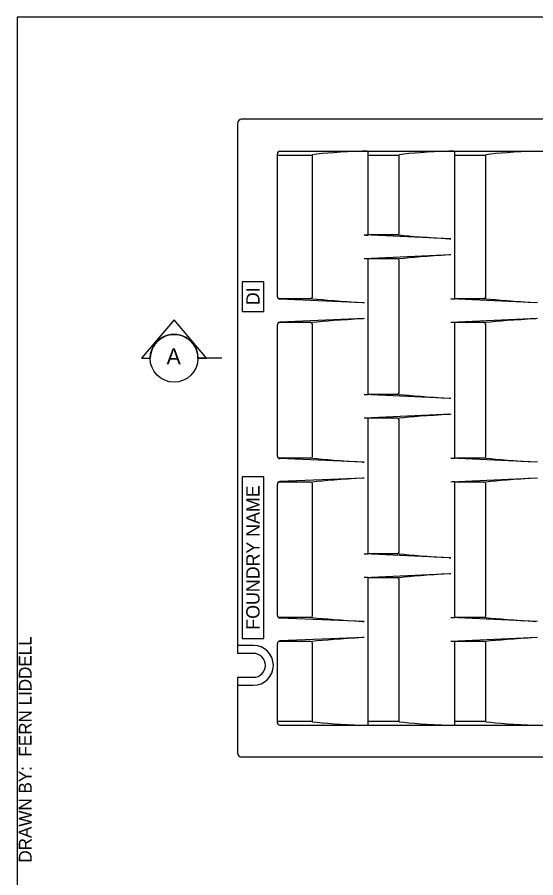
# Model space of a CAD drawing. Extents: x 99862 to 103151, y 100000 to 102076.
# Drawn here: x 99862 to 100513, y 100995 to 102076 of the extents above; entities that cross this region are included whole.
import ezdxf

# ---------------------------------------------------------------- set-up
doc = ezdxf.new("R2010")
doc.units = 0
for name, color, linetype in [('Level 1', 7, 'Continuous'), ('Level 11', 7, 'Continuous'), ('Level 2', 7, 'Continuous'), ('Level 20', 7, 'Continuous'), ('Level 62', 7, 'Continuous'), ('Level 9', 7, 'Continuous')]:
    doc.layers.add(name, color=color, linetype=linetype)

msp = doc.modelspace()

# ---------------------------------------------------------------- linework, layer by layer
at = {"layer": 'Level 1'}
msp.add_lwpolyline([(99862, 99999.5), (103151, 99999.5), (103151, 102075.5), (99862, 102075.5)], close=True, dxfattribs=at)
at = {"layer": 'Level 11'}
for p, q in [((100158.5, 101286.8), (100138.5, 101286.8)), ((100158.5, 101276.8), (100138.5, 101276.8)), ((100158.5, 101246.7), (100138.5, 101246.7)), ((100158.5, 101236.7), (100138.5, 101236.7))]:
    msp.add_line(p, q, dxfattribs=at)
for points in [[(100144.3, 101706), (100171.4, 101706), (100171.4, 101743.2), (100144.3, 101743.2)], [(100144.3, 101295.3), (100171.4, 101295.3), (100171.4, 101498.4), (100144.3, 101498.4)]]:
    msp.add_lwpolyline(points, close=True, dxfattribs=at)
for radius in [25, 15]:
    msp.add_arc((100158.5, 101261.8), radius, 270, 90, dxfattribs=at)
at = {"layer": 'Level 2'}
for p, q in [((100138.5, 101942.1), (100138.5, 101276.8)), ((101094, 101947.3), (100143.7, 101947.3)), ((100191.7, 101907.2), (101059.2, 101907.2)), ((100302.4, 101802.1), (100302.4, 101906.9)), ((100411.2, 101722.1), (100411.2, 101906.9)), ((100188.5, 101904.1), (100188.5, 101724.6)), ((100188.5, 101902.2), (100232.5, 101902.2)), ((100232.5, 101902.2), (100232.5, 101902.8)), ((100232.5, 101889.1), (100232.5, 101902.2)), ((100302.4, 101902.2), (100341.3, 101902.2)), ((100341.3, 101902.2), (100341.3, 101902.8)), ((100341.3, 101804.3), (100341.3, 101902.2)), ((100411.2, 101902.2), (100450.1, 101902.2)), ((100450.1, 101902.2), (100450.1, 101902.8)), ((100450.1, 101724.2), (100450.1, 101902.2)), ((100232.5, 101724.2), (100232.5, 101889.1)), ((100406.2, 101797.2), (100297.4, 101802.2)), ((100339.2, 101802.2), (100302.4, 101802.2)), ((100406.2, 101777.1), (100297.4, 101772.1)), ((100302.4, 101602), (100302.4, 101772.2)), ((100339.2, 101772.1), (100302.4, 101772.1)), ((100341.3, 101604.1), (100341.3, 101770.1)), ((100230.4, 101722.1), (100189.8, 101722.1)), ((100297.4, 101717.1), (100191.5, 101721.5)), ((100515, 101717.1), (100406.2, 101722.1)), ((100448, 101722.1), (100411.2, 101722.1)), ((100188.5, 101689.5), (100188.5, 101524.5)), ((100230.4, 101692.1), (100189.8, 101692.1)), ((100297.4, 101697.1), (100191.5, 101692.7)), ((100232.5, 101524), (100232.5, 101690)), ((100515, 101697.1), (100406.2, 101692.1)), ((100411.2, 101521.9), (100411.2, 101692.1)), ((100448, 101692.1), (100411.2, 101692.1)), ((100450.1, 101524), (100450.1, 101690)), ((100406.2, 101597), (100297.4, 101602)), ((100339.2, 101602), (100302.4, 101602)), ((100406.2, 101577), (100297.4, 101572)), ((100302.4, 101401.8), (100302.4, 101572)), ((100339.2, 101572), (100302.4, 101572)), ((100341.3, 101404), (100341.3, 101569.9)), ((100230.4, 101522), (100189.8, 101522)), ((100297.4, 101517), (100191.5, 101521.4)), ((100515, 101517), (100406.2, 101522)), ((100448, 101522), (100411.2, 101522)), ((100297.4, 101496.9), (100191.5, 101492.5)), ((100515, 101496.9), (100406.2, 101491.9)), ((100188.5, 101489.4), (100188.5, 101324.3)), ((100230.4, 101491.9), (100189.8, 101491.9)), ((100232.5, 101323.9), (100232.5, 101489.8)), ((100411.2, 101321.8), (100411.2, 101492)), ((100448, 101491.9), (100411.2, 101491.9)), ((100450.1, 101323.9), (100450.1, 101489.8)), ((100406.2, 101396.9), (100297.4, 101401.9)), ((100339.2, 101401.9), (100302.4, 101401.9)), ((100406.2, 101376.8), (100297.4, 101371.8)), ((100302.4, 101187.1), (100302.4, 101371.9)), ((100339.2, 101371.8), (100302.4, 101371.8)), ((100341.3, 101191.7), (100341.3, 101369.8)), ((100230.4, 101321.8), (100189.8, 101321.8)), ((100515, 101316.8), (100406.2, 101321.8)), ((100448, 101321.8), (100411.2, 101321.8)), ((100297.4, 101316.8), (100191.5, 101321.2)), ((100188.5, 101289.2), (100188.5, 101189.8)), ((100230.4, 101291.8), (100189.8, 101291.8)), ((100297.4, 101296.8), (100191.5, 101292.4)), ((100232.5, 101204.8), (100232.5, 101289.7)), ((100515, 101296.8), (100406.2, 101291.8)), ((100411.2, 101187.1), (100411.2, 101291.8)), ((100448, 101291.8), (100411.2, 101291.8)), ((100450.1, 101191.7), (100450.1, 101289.7)), ((100138.5, 101246.7), (100138.5, 101151.9)), ((100232.5, 101191.7), (100232.5, 101204.8)), ((100188.5, 101191.7), (100232.5, 101191.7)), ((100232.5, 101191.1), (100232.5, 101191.7)), ((100302.4, 101191.7), (100341.3, 101191.7)), ((100341.3, 101191.1), (100341.3, 101191.7)), ((100411.2, 101191.7), (100450.1, 101191.7)), ((100450.1, 101191.1), (100450.1, 101191.7)), ((100191.7, 101186.7), (101059.2, 101186.7)), ((101094, 101146.7), (100143.7, 101146.7))]:
    msp.add_line(p, q, dxfattribs=at)
for centre, radius, start, end in [((100143.7, 101942.1), 5.22, 90, 180), ((100191.7, 101904.1), 3.13, 90, 180), ((100339.2, 101804.3), 2.09, 270, 0), ((100339.2, 101770.1), 2.09, 0, 90), ((100191.7, 101724.6), 3.13, 180, 267.3974), ((100230.4, 101724.2), 2.09, 270, 0), ((100448, 101724.2), 2.09, 270, 0), ((100191.7, 101689.5), 3.13, 92.6026, 180), ((100230.4, 101690), 2.09, 0, 90), ((100448, 101690), 2.09, 0, 90), ((100339.2, 101604.1), 2.09, 270, 0), ((100339.2, 101569.9), 2.09, 0, 90), ((100191.7, 101524.5), 3.13, 180, 267.3974), ((100230.4, 101524), 2.09, 270, 0), ((100448, 101524), 2.09, 270, 0), ((100191.7, 101489.4), 3.13, 92.6026, 180), ((100230.4, 101489.8), 2.09, 0, 90), ((100448, 101489.8), 2.09, 0, 90), ((100339.2, 101404), 2.09, 270, 0), ((100339.2, 101369.8), 2.09, 0, 90), ((100191.7, 101324.3), 3.13, 180, 267.3974), ((100230.4, 101323.9), 2.09, 270, 0), ((100448, 101323.9), 2.09, 270, 0), ((100191.7, 101289.2), 3.13, 92.6026, 180), ((100230.4, 101289.7), 2.09, 0, 90), ((100448, 101289.7), 2.09, 0, 90), ((100191.7, 101189.8), 3.13, 180, 270), ((100143.7, 101151.9), 5.22, 180, 270)]:
    msp.add_arc(centre, radius, start, end, dxfattribs=at)
for centre, major_axis, ratio, start_param, end_param in [((100353.5, 101897.4), (-140.1, 0), 0.076923, 5.141186, 5.755599), ((100297.4, 101906.9), (-5, 0), 0.076923, 4.712389, 5.141186), ((100297.4, 101906.9), (-5, 0), 0.076923, 3.141593, 4.712389), ((100462.4, 101897.4), (-140.1, 0), 0.076923, 5.141186, 5.755599), ((100406.2, 101906.9), (-5, 0), 0.076923, 4.712389, 5.141186), ((100406.2, 101906.9), (-5, 0), 0.076923, 3.141593, 4.712389), ((100571.2, 101897.4), (-140.1, 0), 0.076923, 5.141186, 5.755599), ((100297.4, 101802.3), (-5, 0.23), 0.035758, 1.572424, 3.14322), ((100462.4, 101799.2), (-140.1, 6.4), 0.035758, 0.529214, 1.143627), ((100406.2, 101797.3), (-5, 0.23), 0.035758, 1.143627, 1.572424), ((100462.4, 101775.1), (140.1, 6.4), 0.035758, 1.997966, 2.612379), ((100406.2, 101777), (5, 0.23), 0.035758, 1.569169, 1.997966), ((100297.4, 101772), (5, 0.23), 0.035758, 6.281558, 7.852354), ((100353.5, 101719.1), (-140.1, 6.4), 0.035758, 0.529214, 1.143627), ((100406.2, 101722.3), (-5, 0.23), 0.035758, 1.572424, 3.14322), ((100571.2, 101719.1), (-140.1, 6.4), 0.035758, 0.529214, 1.143627), ((100297.4, 101717.3), (-5, 0.23), 0.035758, 1.143627, 1.572424), ((100353.5, 101695.1), (140.1, 6.4), 0.035758, 1.997966, 2.612379), ((100297.4, 101696.9), (5, 0.23), 0.035758, 1.569169, 1.997966), ((100406.2, 101691.9), (5, 0.23), 0.035758, 6.281558, 7.852354), ((100571.2, 101695.1), (140.1, 6.4), 0.035758, 1.997966, 2.612379), ((100297.4, 101602.2), (-5, 0.23), 0.035758, 1.572424, 3.14322), ((100462.4, 101599), (-140.1, 6.4), 0.035758, 0.529214, 1.143627), ((100406.2, 101597.2), (-5, 0.23), 0.035758, 1.143627, 1.572424), ((100297.4, 101571.8), (5, 0.23), 0.035758, 6.281558, 7.852354), ((100462.4, 101575), (140.1, 6.4), 0.035758, 1.997966, 2.612379), ((100406.2, 101576.8), (5, 0.23), 0.035758, 1.569169, 1.997966), ((100353.5, 101519), (-140.1, 6.4), 0.035758, 0.529214, 1.143627), ((100297.4, 101517.1), (-5, 0.23), 0.035758, 1.143627, 1.572424), ((100406.2, 101522.1), (-5, 0.23), 0.035758, 1.572424, 3.14322), ((100571.2, 101519), (-140.1, 6.4), 0.035758, 0.529214, 1.143627), ((100353.5, 101494.9), (140.1, 6.4), 0.035758, 1.997966, 2.612379), ((100297.4, 101496.8), (5, 0.23), 0.035758, 1.569169, 1.997966), ((100571.2, 101494.9), (140.1, 6.4), 0.035758, 1.997966, 2.612379), ((100406.2, 101491.8), (5, 0.23), 0.035758, 6.281558, 7.852354), ((100297.4, 101402), (-5, 0.23), 0.035758, 1.572424, 3.14322), ((100462.4, 101398.9), (-140.1, 6.4), 0.035758, 0.529214, 1.143627), ((100406.2, 101397), (-5, 0.23), 0.035758, 1.143627, 1.572424), ((100462.4, 101374.8), (140.1, 6.4), 0.035758, 1.997966, 2.612379), ((100406.2, 101376.7), (5, 0.23), 0.035758, 1.569169, 1.997966), ((100297.4, 101371.7), (5, 0.23), 0.035758, 6.281558, 7.852354), ((100353.5, 101318.8), (-140.1, 6.4), 0.035758, 0.529214, 1.143627), ((100406.2, 101322), (-5, 0.23), 0.035758, 1.572424, 3.14322), ((100571.2, 101318.8), (-140.1, 6.4), 0.035758, 0.529214, 1.143627), ((100297.4, 101317), (-5, 0.23), 0.035758, 1.143627, 1.572424), ((100353.5, 101294.8), (140.1, 6.4), 0.035758, 1.997966, 2.612379), ((100297.4, 101296.6), (5, 0.23), 0.035758, 1.569169, 1.997966), ((100406.2, 101291.6), (5, 0.23), 0.035758, 6.281558, 7.852354), ((100571.2, 101294.8), (140.1, 6.4), 0.035758, 1.997966, 2.612379), ((100353.5, 101196.5), (-140.1, 0), 0.076923, 0.527586, 1.142), ((100297.4, 101187.1), (-5, 0), 0.076923, 1.142, 1.570796), ((100297.4, 101187.1), (-5, 0), 0.076923, 1.570796, 3.141593), ((100462.4, 101196.5), (-140.1, 0), 0.076923, 0.527586, 1.142), ((100406.2, 101187.1), (-5, 0), 0.076923, 1.142, 1.570796), ((100406.2, 101187.1), (-5, 0), 0.076923, 1.570796, 3.141593), ((100571.2, 101196.5), (-140.1, 0), 0.076923, 0.527586, 1.142)]:
    msp.add_ellipse(centre, major_axis=major_axis, ratio=ratio, start_param=start_param, end_param=end_param, dxfattribs=at)
at = {"layer": 'Level 9'}
for p, q in [((100058.9, 101695.7), (100018.2, 101647.3)), ((100099.5, 101647.3), (100058.9, 101695.7)), ((100018.2, 101647.3), (100028.9, 101647.3)), ((100088.9, 101647.3), (100099.5, 101647.3)), ((100118.9, 101647.3), (100088.9, 101647.3))]:
    msp.add_line(p, q, dxfattribs=at)
msp.add_circle((100058.9, 101647.3), 30, dxfattribs=at)
msp.add_arc((100058.9, 101647.3), 30, 359.9978, 180.0022, dxfattribs=at)

# ---------------------------------------------------------------- texts
at = {"layer": 'Level 11'}
for s, height, p in [('DI', 16.7, (100166.2, 101714)), ('FOUNDRY NAME', 16.698, (100166.2, 101306.6))]:
    msp.add_text(s, height=height, rotation=90, dxfattribs=at).set_placement(p)
at = {"layer": 'Level 20'}
msp.add_text('A', height=20, dxfattribs=at).set_placement((100049.5, 101639.7))
at = {"layer": 'Level 62'}
msp.add_text('DRAWN BY:  FERN LIDDELL', height=16, rotation=90, dxfattribs=at).set_placement((99880, 101014.1))

doc.saveas('drawing.dxf')
